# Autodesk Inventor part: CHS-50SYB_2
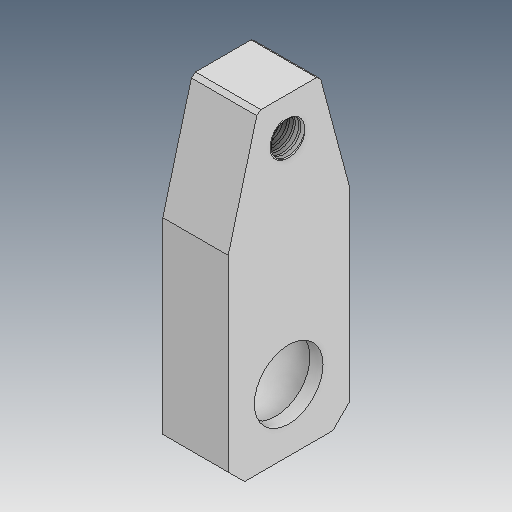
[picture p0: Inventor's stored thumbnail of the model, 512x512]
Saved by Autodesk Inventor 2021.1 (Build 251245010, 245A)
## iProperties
Created: 2019-04
Part Number: CHS-50SYB_2
Material: Ogólny
Document SubType Name: Modeling
Designer: user
Density: 1 g/cm^3
Appearance: Domyślna
Author: user
Revision Number: ÈÎºÎ
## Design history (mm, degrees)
feature "ÊäÈë1"
node "Bryła1"
